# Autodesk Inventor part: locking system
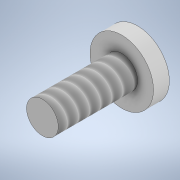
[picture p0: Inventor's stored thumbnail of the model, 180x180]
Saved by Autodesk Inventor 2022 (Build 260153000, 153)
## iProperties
Created: 2021-07
Part Number: locking system
Material: Generic
Document SubType Name: Modeling
Designer: Hp
Density: 1 g/cm^3
Appearance: Default
Author: Hp
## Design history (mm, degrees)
sketch "Sketch1"
  geometry: C1 r 20 at (0, 0); 1 further point
  constraints: 1 centre point, 1 coincident
  dimensions: "d0" = 40 diameter of C1
extrude "Extrusion1" new body sketch "Sketch1" distance "d1" = 10; taper "d2" = 0 deg
sketch "Sketch2"
  geometry: C1 r 10 at (0, 0); 1 further point
  constraints: 1 centre point, 1 coincident
  dimensions: "d3" = 20 diameter of C1
extrude "Extrusion2" join sketch "Sketch2" distance "d4" = 50; taper "d5" = 0 deg
thread "Thread1" dims "d6" = 51.6, "d7" = 0
body "Solid1"
